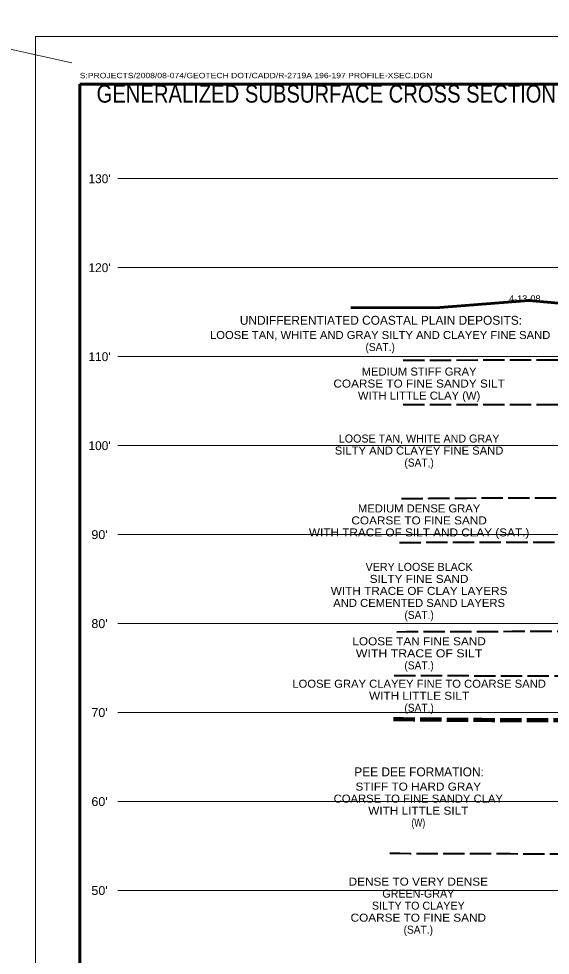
# Model space of a CAD drawing. Extents: x -582 to 653, y -817 to -3.
# Drawn here: x 63.9 to 123.7, y -262.8 to -157.5 of the extents above; entities that cross this region are included whole.
import ezdxf
from ezdxf.enums import TextEntityAlignment as Align

# ---------------------------------------------------------------- set-up
doc = ezdxf.new("R2010")
doc.units = 0
doc.header["$LTSCALE"] = 0.4
doc.linetypes.add('LONG_DASHED', pattern=[7.5, 6, -1.5])
for name, color, linetype, lineweight in [('26', 7, 'LONG_DASHED', 40), ('27', 7, 'Continuous', 40), ('63', 7, 'Continuous', 35), ('7', 7, 'Continuous', 13)]:
    doc.layers.add(name, color=color, linetype=linetype, lineweight=lineweight)
doc.layers.add('29', color=7, linetype='Continuous')

msp = doc.modelspace()

# ---------------------------------------------------------------- linework, layer by layer
at = {"layer": '26', "linetype": 'Continuous', "lineweight": 60}
msp.add_lwpolyline([(101.2906, -190.0029), (111.2906, -189.9729), (121.2906, -189.1829), (128.7906, -189.8429)], dxfattribs=at)
at = {"layer": '26'}
for points in [[(107.1793, -195.8668), (123.7732, -195.8429), (127.5406, -195.843), (130.0407, -195.843), (139.0865, -195.8668)], [(107.1793, -200.8668), (123.7732, -200.8429), (127.5406, -200.843), (130.0407, -200.843), (139.0865, -200.8668)]]:
    msp.add_lwpolyline(points, dxfattribs=at)
for points in [[(106.9787, -211.4306), (123.7732, -211.343), (127.5406, -211.343), (130.0407, -211.343), (135.3741, -211.9327), (138.8859, -212.9368)], [(106.778, -216.3508), (123.7732, -216.343), (127.5406, -216.343), (130.0407, -216.343), (141.2906, -216.1854)], [(106.477, -226.3919), (123.7732, -226.343), (127.5406, -226.343), (130.0407, -226.343), (141.2906, -225.8935)], [(106.176, -231.3121), (123.7732, -231.343), (127.5406, -231.343), (130.0407, -231.343), (141.2906, -230.8935)], [(105.6743, -251.2939), (123.7732, -251.3429), (127.5406, -251.3429), (130.0406, -251.3429), (141.2906, -250.8935)]]:
    msp.add_spline(points, degree=3, dxfattribs=at)
at = {"layer": '26', "lineweight": 100}
msp.add_spline([(106.0757, -236.2322), (123.7732, -236.343), (127.5406, -236.343), (130.0407, -236.343), (141.2906, -236.1853)], degree=3, dxfattribs=at)
at = {"layer": '27', "lineweight": 13}
msp.add_line((69.9128, -162.4726), (47.7228, -157.501), dxfattribs=at)
at = {"layer": '63', "lineweight": 13}
for q in [(65.8298, -329.4952), (175.8298, -159.4952)]:
    msp.add_line((65.8298, -159.4952), q, dxfattribs=at)
at = {"layer": '63', "lineweight": 60}
for p in [(70.8298, -325.4952), (170.8298, -164.8424)]:
    msp.add_line(p, (70.8298, -164.8424), dxfattribs=at)
at = {"layer": '7'}
for p, q in [((75.0972, -175.4729), (166.391, -175.4729)), ((75.0972, -185.4729), (166.391, -185.4729)), ((75.0972, -195.4729), (127.5406, -195.4729)), ((75.0972, -205.4729), (127.5406, -205.4729)), ((75.0972, -215.4729), (127.5406, -215.4729)), ((75.0972, -225.4729), (127.5406, -225.4729)), ((75.0972, -235.4729), (127.5406, -235.4729)), ((75.0972, -245.4729), (127.5406, -245.4729)), ((75.0972, -255.4729), (127.5406, -255.4729))]:
    msp.add_line(p, q, dxfattribs=at)

# ---------------------------------------------------------------- texts
at = {"layer": '27', "width": 1.1}
msp.add_text('4-13-08', height=0.6976, dxfattribs=at).set_placement((120.8528, -189.2914), align=Align.CENTER)
at = {"layer": '29'}
for s, height, p in [('UNDIFFERENTIATED COASTAL PLAIN DEPOSITS:', 1, (104.6802, -191.895)), ('LOOSE TAN, WHITE AND GRAY', 0.9, (108.9706, -205.1353)), ('VERY LOOSE BLACK', 0.9, (108.9706, -219.5585)), ('PEE DEE FORMATION:', 1, (108.9674, -242.6498)), ('GREEN-GRAY', 0.9, (108.8795, -256.2834)), ('SILTY TO CLAYEY', 0.9, (108.8794, -257.6334))]:
    msp.add_text(s, height=height, dxfattribs=at).set_placement(p, align=Align.CENTER)
for s, width, p in [('LOOSE TAN, WHITE AND GRAY SILTY AND CLAYEY FINE SAND', 1.05, (104.5922, -193.4982)), ('(SAT.)', 0.95, (104.5923, -194.8482)), ('MEDIUM STIFF GRAY', 1.05, (108.9706, -197.6061)), ('COARSE TO FINE SANDY SILT', 1.1, (108.9707, -198.9561)), ('WITH LITTLE CLAY (W)', 1.05, (108.9706, -200.3061)), ('SILTY AND CLAYEY FINE SAND', 1.05, (108.9706, -206.4853)), ('(SAT,)', 0.95, (108.9707, -207.8353)), ('MEDIUM DENSE GRAY', 1.05, (108.9706, -212.9859)), ('COARSE TO FINE SAND', 1.1, (108.9706, -214.3359)), ('WITH TRACE OF SILT AND CLAY (SAT.)', 1.1, (108.9706, -215.6859)), ('SILTY FINE SAND', 1.1, (108.9706, -220.9085)), ('WITH TRACE OF CLAY LAYERS', 1.1, (108.9707, -222.2585)), ('AND CEMENTED SAND LAYERS', 1.05, (108.9706, -223.6085)), ('(SAT.)', 0.95, (108.9707, -224.9585)), ('LOOSE TAN FINE SAND', 1.1, (108.9706, -227.9212)), ('WITH TRACE OF SILT', 1.15, (108.9706, -229.2712)), ('(SAT.)', 0.95, (108.9707, -230.6212)), ('LOOSE GRAY CLAYEY FINE TO COARSE SAND', 1.05, (108.9707, -232.6909)), ('WITH LITTLE SILT', 1.1, (108.9706, -234.0409)), ('(SAT.)', 0.95, (108.9707, -235.3909)), ('STIFF TO HARD GRAY', 1.1, (108.8794, -244.253)), ('COARSE TO FINE SANDY CLAY', 1.05, (108.8795, -245.603)), ('WITH LITTLE SILT', 1.1, (108.8794, -246.953)), ('(W)', 0.8, (108.8794, -248.303)), ('DENSE TO VERY DENSE', 1.1, (108.8794, -254.9334)), ('COARSE TO FINE SAND', 1.1, (108.8794, -258.9834)), ('(SAT.)', 0.95, (108.8795, -260.3334))]:
    msp.add_text(s, height=0.9, dxfattribs=dict(at, width=width)).set_placement(p, align=Align.CENTER)
at = {"layer": '63', "width": 1.2}
msp.add_text('S:PROJECTS/2008/08-074/GEOTECH DOT/CADD/R-2719A 196-197 PROFILE-XSEC.DGN', height=0.6, dxfattribs=at).set_placement((70.8134, -164.1835))
at = {"layer": '63'}
for s, height, width, p in [('GENERALIZED SUBSURFACE CROSS SECTION THROUGH END BENT No. 2 (LEFT LANE)', 2, 0.85, (120.8298, -166.9305)), ("90'", 1, 1.05, (73.0358, -215.9837)), ("80'", 1, 1.05, (73.0358, -225.9837)), ("70'", 1, 1.05, (73.0358, -235.9837)), ("60'", 1, 1.05, (73.0358, -245.9837)), ("50'", 1, 1.05, (73.0358, -255.9837))]:
    msp.add_text(s, height=height, dxfattribs=dict(at, width=width)).set_placement(p, align=Align.CENTER)
for s, p in [("130'", (73.0357, -175.9837)), ("120'", (73.0357, -185.9837)), ("110'", (73.0358, -195.9837)), ("100'", (73.0357, -205.9837))]:
    msp.add_text(s, height=1, dxfattribs=at).set_placement(p, align=Align.CENTER)

doc.saveas('drawing.dxf')
